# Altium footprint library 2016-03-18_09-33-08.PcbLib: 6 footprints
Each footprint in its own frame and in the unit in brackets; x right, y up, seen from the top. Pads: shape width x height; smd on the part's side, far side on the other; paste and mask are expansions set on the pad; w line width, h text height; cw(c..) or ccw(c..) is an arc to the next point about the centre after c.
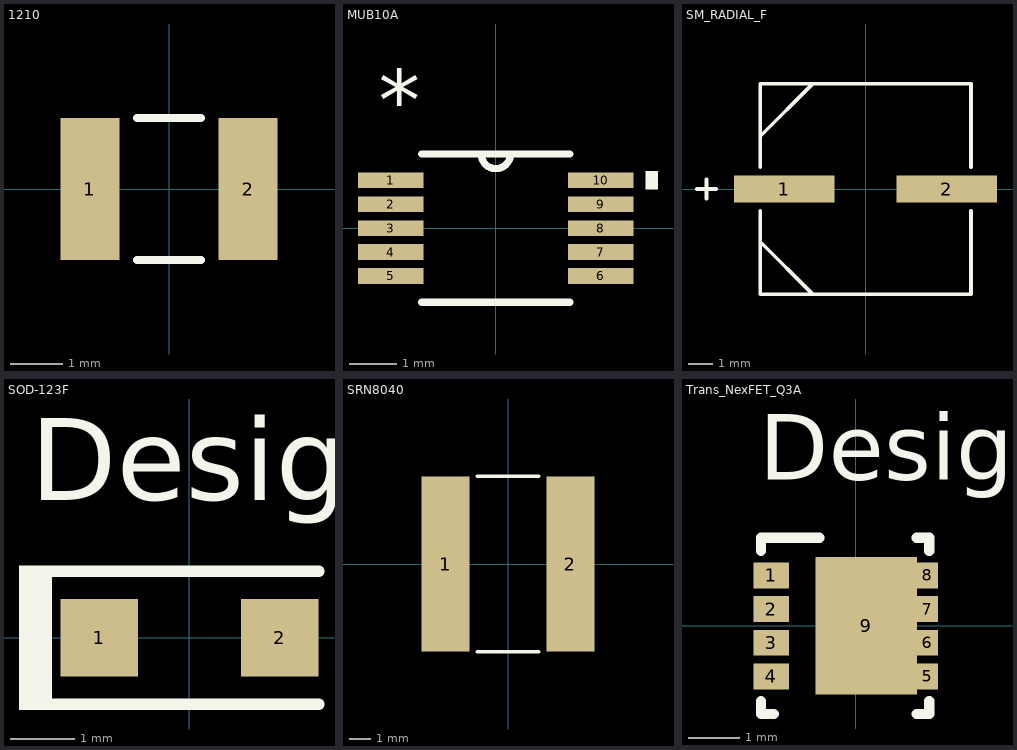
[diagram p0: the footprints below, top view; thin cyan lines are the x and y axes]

## 1210 [mil]
pads (2):
  rect 44x106 smd: 1(-59,0) 2(59,0)
Top Overlay:
  lines w6: -23.9,-53 23.9,-53 ; -23.9,53 23.9,53

## MUB10A [mil]
pads (10):
  rect 54x13 smd: 1(-86.5,39.37) 2(-86.5,19.68) 3(-86.5,0) 4(-86.5,-19.68) 5(-86.5,-39.37) 6(86.5,-39.37) 7(86.5,-19.68) 8(86.5,0) 9(86.5,19.68) 10(86.5,39.37)
Top Overlay:
  region: 123.5,46.87 133.5,46.87 133.5,31.87 123.5,31.87
  lines w6: -61,-61 61,-61 ; -61,61 61,61 ; -12,61 ccw(c0,61) 12,61
  text "*" at -96.5,80.87 h50

## SM_RADIAL_F [mil]
pads (2):
  rect 160x43 smd: 1(-129,0) 2(129,0)
Top Overlay:
  lines w6: -268,0 -238,0 ; -253,-15 -253,15 ; -167.5,-83.75 -83.75,-167.5 ; -167.5,-34.6 -167.5,-167.5 167.5,-167.5 167.5,-34.6 ; -167.5,34.6 -167.5,167.5 167.5,167.5 167.5,34.6 ; -167.5,83.75 -83.75,167.5

## SOD-123F [mm]
pads (2):
  rect 1.2x1.2 smd paste-0.05 mask+0.051: 1(-1.4,0) 2(1.4,0)
Top Overlay:
  region: -2.642,1.118 -2.642,-1.118 -2.134,-1.118 -2.134,1.118
  lines w0.178: -2.311,-1.029 2.007,-1.029 ; -2.311,1.029 2.007,1.029
  text "Designator9" at -2.464,2.134 h1.27

## SRN8040 [mm]
pads (2):
  rect 2.2x8 smd: 1(-2.85,0) 2(2.85,0)
Top Overlay:
  lines w0.152: -1.417,-4 1.417,-4 ; -1.417,4 1.417,4

## Trans_NexFET_Q3A [mm]
pads (9):
  rect 0.68x0.5 smd paste-0.327 mask+0.076: 1(-1.625,0.975) 2(-1.625,0.325) 3(-1.625,-0.325) 4(-1.625,-0.975)
  rect 0.41x0.5 smd paste-0.237 mask+0.076: 5(1.385,-0.975) 6(1.385,-0.325) 7(1.385,0.325) 8(1.385,0.975)
  rect 1.96x2.65 smd paste-1.312 mask+0.076: 9(0.205,0)
Top Overlay:
  lines w0.2: -1.825,-1.453 -1.825,-1.7 -1.578,-1.7 ; -1.825,1.453 -1.825,1.7 -0.7,1.7 ; 1.178,-1.7 1.425,-1.7 1.425,-1.453 ; 1.178,1.7 1.425,1.7 1.425,1.453
  text "Designator9" at -1.854,2.819 h1.27
Top Paste:
  region: -1.85,1.145 -1.85,0.805 -1.4,0.805 -1.4,1.145
  region: -1.85,0.495 -1.85,0.155 -1.4,0.155 -1.4,0.495
  region: -1.84,-0.155 -1.84,-0.495 -1.39,-0.495 -1.39,-0.155
  region: -1.85,-0.805 -1.85,-1.145 -1.4,-1.145 -1.4,-0.805
  region: 1.025,-0.805 1.025,-1.145 1.475,-1.145 1.475,-0.805
  region: 1.025,-0.155 1.025,-0.495 1.475,-0.495 1.475,-0.155
  region: 1.025,0.495 1.025,0.155 1.475,0.155 1.475,0.495
  region: 1.025,1.145 1.025,0.805 1.475,0.805 1.475,1.145
  region: -0.655,0.125 0.795,0.125 0.795,1.145 -0.655,1.145
  region: -0.655,-1.145 0.795,-1.145 0.795,-0.125 -0.655,-0.125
